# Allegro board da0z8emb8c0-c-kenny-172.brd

Outline 225.17 x 128 mm; copper layers: TOP, SGND, IN1, IN2, SVCC, IN3, SGND1, BOTTOM. Coordinates in mm from the lower left corner of the outline.

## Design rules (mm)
constraint set DEFAULT: min track width 0.102
net group DFP-S4.5W4(3.5)-T123B: nets INT_HDMI_AUXN INT_HDMI_AUXP
net group W10-T123B: nets FAN_PWM FAN_PWM_C
net group DFP-S3.5W4(3.5)-T13B: nets CLKA0 CLKA0B CLKA1 CLKA1B M_A_DQSN0 M_A_DQSN1 M_A_DQSN2 M_A_DQSN3 M_A_DQSN4 M_A_DQSN5 M_A_DQSN6 M_A_DQSN7 M_A_DQSP0 M_A_DQSP1 M_A_DQSP2 M_A_DQSP3 M_A_DQSP4 M_A_DQSP5 M_A_DQSP6 M_A_DQSP7 M_B_DQSN0 M_B_DQSN1 M_B_DQSN2 M_B_DQSN3 M_B_DQSN4 M_B_DQSN5 M_B_DQSN6 M_B_DQSN7 M_B_DQSP0 M_B_DQSP1 M_B_DQSP2 M_B_DQSP3 M_B_DQSP4 M_B_DQSP5 M_B_DQSP6 M_B_DQSP7 WCKA0_0 WCKA0_1 WCKA0B_0 WCKA0B_1 WCKA1_0 WCKA1_1 WCKA1B_0 WCKA1B_1
net group DFP-S4.5W4(3.5)-T13B: nets C_IN_CLK#_R C_IN_CLK_R C_TX0_HDMI+_R C_TX0_HDMI-_R C_TX1_HDMI+_R C_TX1_HDMI-_R C_TX2_HDMI+_R C_TX2_HDMI-_R CLK_PCIE_LANN_R CLK_PCIE_LANP_R CLK_PCIE_SSDN_C CLK_PCIE_SSDN_R CLK_PCIE_SSDP_C CLK_PCIE_SSDP_R CLK_PCIE_WLANN_R CLK_PCIE_WLANP_R GFX_TX0N_C GFX_TX0P_C GFX_TX1N_C GFX_TX1P_C GFX_TX2N_C GFX_TX2P_C GFX_TX3N_C GFX_TX3P_C IN_CLK IN_CLK# IN_D0 IN_D0# IN_D1 IN_D1# IN_D2 IN_D2# INT_EDP_AUXN INT_EDP_AUXN_C INT_EDP_AUXP INT_EDP_AUXP_C INT_EDP_TXN0 INT_EDP_TXN0_C INT_EDP_TXN1 INT_EDP_TXN1_C INT_EDP_TXN2 INT_EDP_TXN2_C INT_EDP_TXN3 INT_EDP_TXN3_C INT_EDP_TXP0 INT_EDP_TXP0_C INT_EDP_TXP1 INT_EDP_TXP1_C INT_EDP_TXP2 INT_EDP_TXP2_C INT_EDP_TXP3 INT_EDP_TXP3_C INT_HDMICLK+_OUT INT_HDMICLK-_OUT INT_HDMITX0N_OUT INT_HDMITX0P_OUT INT_HDMITX1N_OUT INT_HDMITX1P_OUT INT_HDMITX2N_OUT INT_HDMITX2P_OUT PCIE_RXN0_SSD PCIE_RXN3_SSD PCIE_RXN4_LAN PCIE_RXN5_WLAN PCIE_RXN13_SSD_C PCIE_RXN14_SSD_C PCIE_RXN15_SSD_C PCIE_RXN16_SSD_C PCIE_RXN_LAN_L PCIE_RXP0_SSD PCIE_RXP3_SSD PCIE_RXP4_LAN PCIE_RXP5_WLAN PCIE_RXP13_SSD_C PCIE_RXP14_SSD_C PCIE_RXP15_SSD_C PCIE_RXP16_SSD_C PCIE_RXP_LAN_L PCIE_TXN0_SSD PCIE_TXN0_SSD_C PCIE_TXN1_SSD PCIE_TXN1_SSD_C PCIE_TXN2_SSD PCIE_TXN2_SSD_C PCIE_TXN3_SSD PCIE_TXN3_SSD_C PCIE_TXN4_LAN PCIE_TXN4_LAN_C PCIE_TXN5_WLAN PCIE_TXN5_WLAN_C PCIE_TXP0_SSD PCIE_TXP0_SSD_C PCIE_TXP1_SSD PCIE_TXP1_SSD_C PCIE_TXP2_SSD PCIE_TXP2_SSD_C PCIE_TXP3_SSD PCIE_TXP3_SSD_C PCIE_TXP4_LAN PCIE_TXP4_LAN_C PCIE_TXP5_WLAN PCIE_TXP5_WLAN_C PEG_RXN0 PEG_RXN0_C PEG_RXN1 PEG_RXN1_C PEG_RXN2 PEG_RXN2_C PEG_RXN3 PEG_RXN3_C PEG_RXP0 PEG_RXP0_C PEG_RXP1 PEG_RXP1_C PEG_RXP2 PEG_RXP2_C PEG_RXP3 PEG_RXP3_C PEG_TXN0 PEG_TXN1 PEG_TXN2 PEG_TXN3 PEG_TXP0 PEG_TXP1 PEG_TXP2 PEG_TXP3 USB3_SS0RX+ USB3_SS0RX+_RE USB3_SS0RX+_RE_C USB3_SS0RX- USB3_SS0RX-_RE USB3_SS0RX-_RE_C USB3_SS0TX+ USB3_SS0TX+_RE USB3_SS0TX+_RE_C USB3_SS0TX- USB3_SS0TX-_RE USB3_SS0TX-_RE_C USB30_RX0+ USB30_RX0- USB30_RX1+ USB30_RX1+_C USB30_RX1- USB30_RX1-_C USB30_RX2+ USB30_RX2+_C USB30_RX2- USB30_RX2-_C USB30_RX3+ USB30_RX3- USB30_RX+_TYPEC1 USB30_RX+_TYPEC2 USB30_RX-_TYPEC1 USB30_RX-_TYPEC2 USB30_TX0+ USB30_TX0- USB30_TX1+ USB30_TX1+_C USB30_TX1+_C_R USB30_TX1- USB30_TX1-_C USB30_TX1-_C_R USB30_TX2+ USB30_TX2+_C USB30_TX2+_C_R USB30_TX2- USB30_TX2-_C USB30_TX2-_C_R USB30_TX3+ USB30_TX3- USB30_TX+_TYPEC1 USB30_TX+_TYPEC1_C USB30_TX+_TYPEC2 USB30_TX+_TYPEC2_C USB30_TX-_TYPEC1 USB30_TX-_TYPEC1_C USB30_TX-_TYPEC2 USB30_TX-_TYPEC2_C
net group DFP-S6(5)W6.5(5.5)-T13B: nets M_A_CLKN0 M_A_CLKN1 M_A_CLKP0 M_A_CLKP1 M_B_CLKN0 M_B_CLKP0
net group DFP-S6(5.5)W4(3.5)-T13B: nets SATA_RXN0 SATA_RXN0_CN SATA_RXN0_IN SATA_RXN1 SATA_RXN1A_C SATA_RXN_OUT SATA_RXP0 SATA_RXP0_CN SATA_RXP0_IN SATA_RXP1 SATA_RXP1A_C SATA_RXP_OUT SATA_TXN0 SATA_TXN0_CN SATA_TXN0_IN SATA_TXN1 SATA_TXN1A_C SATA_TXN_OUT SATA_TXP0 SATA_TXP0_CN SATA_TXP0_IN SATA_TXP1 SATA_TXP1A_C SATA_TXP_OUT USB1_DM0-_HUB USB1_DM0-_HUB_R USB1_DP0+_HUB USB1_DP0+_HUB_R USBP0+ USBP0- USBP1+_C USBP1+_C_R USBP1+_U14 USBP1-_C USBP1-_C_R USBP1-_U14 USBP2+ USBP2+_C USBP2- USBP2-_C USBP3+ USBP3- USBP4+_DB USBP4-_DB USBP5+_CAM USBP5+_CAM_C USBP5-_CAM USBP5-_CAM_C USBP7+_FP USBP7+_FP_HUB USBP7-_FP USBP7-_FP_HUB USBP8+_TS USBP8-_TS USBP8_TS+_C USBP8_TS-_C USBP_TYPC+_C USBP_TYPC-_C
net group DFP-S11.5(11: nets MDI0+ MDI0+_1 MDI0- MDI0-_1 MDI1+ MDI1+_1 MDI1- MDI1-_1 MDI2+ MDI2+_1 MDI2- MDI2-_1 MDI3+ MDI3+_1 MDI3- MDI3-_1
net group GND: nets GND
net group W4(3.5)-T13B: nets ACZ_RST#_AUDIO ACZ_SDIN0 ACZ_SDOUT_AUDIO ACZ_SYNC_AUDIO BIT_CLK_AUDIO DMIC_CLK DMIC_CLK_L DMIC_DAT DMIC_DAT_L EMMC_CLK EMMC_CLK_R EMMC_CMD EMMC_CMD_R EMMC_DAT0 EMMC_DAT0_R EMMC_DAT1 EMMC_DAT1_R EMMC_DAT2 EMMC_DAT2_R EMMC_DAT3 EMMC_DAT3_R EMMC_DAT4 EMMC_DAT4_R EMMC_DAT5 EMMC_DAT5_R EMMC_DAT6 EMMC_DAT6_R EMMC_DAT7 EMMC_DAT7_R EMMC_RCLK EMMC_RCLK_R M_A_DM0 M_A_DM1 M_A_DM2 M_A_DM3 M_A_DM4 M_A_DM5 M_A_DM6 M_A_DM7 M_A_DQ0 M_A_DQ1 M_A_DQ2 M_A_DQ3 M_A_DQ4 M_A_DQ5 M_A_DQ6 M_A_DQ7 M_A_DQ8 M_A_DQ9 M_A_DQ10 M_A_DQ11 M_A_DQ12 M_A_DQ13 M_A_DQ14 M_A_DQ15 M_A_DQ16 M_A_DQ17 M_A_DQ18 M_A_DQ19 M_A_DQ20 M_A_DQ21 M_A_DQ22 M_A_DQ23 M_A_DQ24 M_A_DQ25 M_A_DQ26 M_A_DQ27 M_A_DQ28 M_A_DQ29 M_A_DQ30 M_A_DQ31 M_A_DQ32 M_A_DQ33 M_A_DQ34 M_A_DQ35 M_A_DQ36 M_A_DQ37 M_A_DQ38 M_A_DQ39 M_A_DQ40 M_A_DQ41 M_A_DQ42 M_A_DQ43 M_A_DQ44 M_A_DQ45 M_A_DQ46 M_A_DQ47 M_A_DQ48 M_A_DQ49 M_A_DQ50 M_A_DQ51 M_A_DQ52 M_A_DQ53 M_A_DQ54 M_A_DQ55 M_A_DQ56 M_A_DQ57 M_A_DQ58 M_A_DQ59 M_A_DQ60 M_A_DQ61 M_A_DQ62 M_A_DQ63 M_A_EVENT# M_A_RST# M_B_DM0 M_B_DM1 M_B_DM2 M_B_DM3 M_B_DM4 M_B_DM5 M_B_DM6 M_B_DM7 M_B_DQ0 M_B_DQ1 M_B_DQ2 M_B_DQ3 M_B_DQ4 M_B_DQ5 M_B_DQ6 M_B_DQ7 M_B_DQ8 M_B_DQ9 M_B_DQ10 M_B_DQ11 M_B_DQ12 M_B_DQ13 M_B_DQ14 M_B_DQ15 M_B_DQ16 M_B_DQ17 M_B_DQ18 M_B_DQ19 M_B_DQ20 M_B_DQ21 M_B_DQ22 M_B_DQ23 M_B_DQ24 M_B_DQ25 M_B_DQ26 M_B_DQ27 M_B_DQ28 M_B_DQ29 M_B_DQ30 M_B_DQ31 M_B_DQ32 M_B_DQ33 M_B_DQ34 M_B_DQ35 M_B_DQ36 M_B_DQ37 M_B_DQ38 M_B_DQ39 M_B_DQ40 M_B_DQ41 M_B_DQ42 M_B_DQ43 M_B_DQ44 M_B_DQ45 M_B_DQ46 M_B_DQ47 M_B_DQ48 M_B_DQ49 M_B_DQ50 M_B_DQ51 M_B_DQ52 M_B_DQ53 M_B_DQ54 M_B_DQ55 M_B_DQ56 M_B_DQ57 M_B_DQ58 M_B_DQ59 M_B_DQ60 M_B_DQ61 M_B_DQ62 M_B_DQ63 PCH_AZ_CODEC_SDIN0_R
net group W4(3.5)-T123B: nets 5V_HSMBCK 5V_HSMBDT 32K_X1 32K_X2 48M_X1 48M_X2 APU_DISP_ON APU_DPST_PWM APU_LVDS_BLON BRIGHT DISP_ON GPU_CLR_REQ6# HDMI_HPD HDMI_HPD_C HDMI_HPD_Q HDMI_SCLK HDMI_SDATA LAN_XTAL1 PCH_BLON_C PCIE_CLKREQ_LAN# PCIE_CLKREQ_WLAN# SI_XTALIN SI_XTALOUT SL_CLK_100M SSD_PCIE_CLKREQ# ULT_EDP_HPD ULT_EDP_HPD_R XIN XOUT XTAL1 XTAL2 XTAL2_R XTALIN XTALOUT
net group W4-T13B: nets APU_SPI_CLK APU_SPI_CLK_R APU_SPI_CLK_TPM APU_SPI_CS0# APU_SPI_CS0#_R APU_SPI_HOLD# APU_SPI_SI APU_SPI_SI_R APU_SPI_SI_TPM APU_SPI_SO APU_SPI_SO_R APU_SPI_SO_TPM APU_SPI_WP APU_SPI_WP_R APU_SVC APU_SVD APU_SVT EC_SPI1_CLK EC_SPI1_CLK_ER EC_SPI1_CLK_R EC_SPI1_SI EC_SPI1_SI_ER EC_SPI1_SI_R EC_SPI1_SO EC_SPI1_SO_ER EC_SPI1_SO_R EC_SPI_CS0# EC_SPI_CS0#_ER EC_SPI_CS0#_R EC_SPI_HOLD# EC_SPI_WP# EC_SPI_WP#_R ESPI_0 ESPI_0_R ESPI_1 ESPI_1_R ESPI_2 ESPI_2_R ESPI_3 ESPI_3_R ESPI_CLK ESPI_CLK_R ESPI_CS# ESPI_CS#_R ESPI_RESET# LAD0 LAD1 LAD2 LAD3 LFRAME_L LPC_PD_L LPCCLK LPCCLK_RUN_L LPCCLK_RUN_L_R PLTRST#_EC PROCHOT_EC SERIRQ SERIRQ_R SPI_TPM_CS SPI_TPM_CS_TPM SVC_APU SVD_APU SVT_APU
net group W5(4.5)-T13B: nets ADBIA0 ADBIA1 CASA0B CASA1B CKEA0 CKEA1 CSA0B_0 CSA1B_0 DDBIA0_0 DDBIA0_1 DDBIA0_2 DDBIA0_3 DDBIA1_0 DDBIA1_1 DDBIA1_2 DDBIA1_3 DQA0_0 DQA0_1 DQA0_2 DQA0_3 DQA0_4 DQA0_5 DQA0_6 DQA0_7 DQA0_8 DQA0_9 DQA0_10 DQA0_11 DQA0_12 DQA0_13 DQA0_14 DQA0_15 DQA0_16 DQA0_17 DQA0_18 DQA0_19 DQA0_20 DQA0_21 DQA0_22 DQA0_23 DQA0_24 DQA0_25 DQA0_26 DQA0_27 DQA0_28 DQA0_29 DQA0_30 DQA0_31 DQA1_0 DQA1_1 DQA1_2 DQA1_3 DQA1_4 DQA1_5 DQA1_6 DQA1_7 DQA1_8 DQA1_9 DQA1_10 DQA1_11 DQA1_12 DQA1_13 DQA1_14 DQA1_15 DQA1_16 DQA1_17 DQA1_18 DQA1_19 DQA1_20 DQA1_21 DQA1_22 DQA1_23 DQA1_24 DQA1_25 DQA1_26 DQA1_27 DQA1_28 DQA1_29 DQA1_30 DQA1_31 DRAM_RST_A EDCA0_0 EDCA0_1 EDCA0_2 EDCA0_3 EDCA1_0 EDCA1_1 EDCA1_2 EDCA1_3 MAA0_0 MAA0_1 MAA0_2 MAA0_3 MAA0_4 MAA0_5 MAA0_6 MAA0_7 MAA0_8 MAA1_0 MAA1_1 MAA1_2 MAA1_3 MAA1_4 MAA1_5 MAA1_6 MAA1_7 MAA1_8 RASA0B RASA1B WEA0B WEA1B
net group W5-T13B: nets CPU_VDD0_RUN_FB_H CPU_VDD0_RUN_FB_L CPU_VDDNB_RUN_FB_H CPU_VDDP_RUN_FB_H CPU_VDDP_RUN_FB_L
net group W6.5(5.5)-T13B: nets M_A_A0 M_A_A1 M_A_A2 M_A_A3 M_A_A4 M_A_A5 M_A_A6 M_A_A7 M_A_A8 M_A_A9 M_A_A10 M_A_A11 M_A_A12 M_A_A13 M_A_ACT# M_A_ALERT# M_A_BG#0 M_A_BG#1 M_A_BS#0 M_A_BS#1 M_A_CAS# M_A_CKE0 M_A_CKE1 M_A_CS#0 M_A_CS#1 M_A_ODT0 M_A_ODT1 M_A_PARITY M_A_RAS# M_A_WE#
net group W6.5(5.25)-T13B: nets M_B_BG#1_R0 M_B_BG#1_R1 M_B_BG#1_R2 M_B_BG#1_R3
net group W6.5(5.25)-T123B: nets M_B_A0 M_B_A1 M_B_A2 M_B_A3 M_B_A4 M_B_A5 M_B_A6 M_B_A7 M_B_A8 M_B_A9 M_B_A10 M_B_A11 M_B_A12 M_B_A13 M_B_ACT# M_B_ALERT# M_B_BG#0 M_B_BG#1 M_B_BS#0 M_B_BS#1 M_B_CAS# M_B_CKE0 M_B_CS#0 M_B_ODT0 M_B_PARITY M_B_RAS# M_B_WE#
net group W8-T123B: nets +1.05V_LAN +5V_PVDD +5VA +AZA_VDD AVDD2 DVDD_IO
net group W12-T123B: nets +3V_EC +3V_LDO_EC +A3VPCU
net group W15-T123B: nets HP-L2 HP-L3 HP-R2 HP-R3 HP_JD# LINE1-L LINE1-R LINE1-VREFO-L LINE1-VREFO-R MIC2-VREFO MVREFDA MVREFDB SENSEA
net group W20-T123B: nets 5447_CC1_CON 5447_CC2_CON +1.5V_RTC +1.8V_SW +1.8V_TPM +1.8V_TPM_VSB +3V_DMIC +3V_GFX +3V_LAN +3V_USB +3V_USB_D +3VPCU +3VPCU_EC +3VPCU_ECPLL +3VPCU_HALL +3VRTC +5V_HDMIC +5V_KB +APU_VDD_33 +APU_VDD_33_S5 +APU_VDDIO_AZ +BAT_RTC +G_SEN_PW +VCCRTC_2 +VDDQ +VDDQ_VTT +VREF_CA0 +VREF_CA1 ECROM_PWR EMMC_VDDI_BYP PBA_PWR PBA_PWR_C PBA_PWR_R VDDBT_RTC VREFC_A0 VREFC_A1 VREFD1_A0 VREFD1_A1 VREFD2_A0 VREFD2_A1 VSTBY_FSPI
net group W30-T123B: nets +VDD_18_S5
net group W40-T123B: nets +0.95VS5 L_SPK+ L_SPK+_1 L_SPK- L_SPK-_1 R_SPK+ R_SPK+_1 R_SPK- R_SPK-_1 RING2 SLEEVE
net group W60-T123B: nets 1.8V_PU9 3.3V_PU9 +1.05V_LAN_REGOUT
net group W65-T123B: nets +601_VCC
net group W70-T123B: nets USBPWRD2
net group W80-T123B: nets +USBPWR0 +USBPWR1 +VIN_BLIGHT
net group W99-T123B: nets +3V_SSD +3V_WLAN_P +3VLCD_CON +3VLCD_CON_R +3VLCD_CON_R_C +5VODD +TYPEC_VBUS

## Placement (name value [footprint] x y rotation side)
C17  4.7u/25V_6  [C0603]  62.72 109.84 90 top
C22  0.1u/16V_4  [C0402]  47.94 109.46 270 top
C23  10u/6.3V_6  [C0603]  47.05 112.13 270 top
C24  *0.1u/16V_4  [C0402]  49.26 112 90 top
C25  0.1u/16V_4  [C0402]  48.27 112 90 top
C28  0.1u/16V_4  [C0402]  54.8 108.57 0 top
C29  *0.1u/16V_4  [C0402]  52.26 113.02 90 top
C30  *4.7u/6.3V_4  [C0402]  40.19 109.21 0 top
C31  *4.7u/6.3V_4  [C0402]  43.75 100.95 0 top
C32  15p/50V_4  [C0402]  43.62 110.98 0 top
C33  15p/50V_4  [C0402]  45.43 110.98 0 top
C37  1000p/50V_4  [C0402]  53.02 108.6 0 top
C39  0.1u/16V_4  [C0402]  43.75 109.59 270 top
C42  0.1u/16V_4  [C0402]  43.75 99.81 0 top
C43  0.1u/10V_2  [C0201]  54.06 103.49 270 bottom
C45  0.1u/16V_4  [C0402]  42.48 109.59 270 top
C51  0.1u/16V_4  [C0402]  40.19 108.06 0 top
C53  0.1u/10V_2  [C0201]  55.18 103.49 270 bottom
C58  0.1u/16V_4  [C0402]  49.34 107.17 90 top
C61  33p/50V_4  [C0402]  56.7 107.17 270 top
C62  0.1u/25V_4  [C0402]  60.54 108.49 0 top
C64  0.1u/16V_4  [C0402]  40.75 106.54 270 bottom
C65  0.1u/16V_4  [C0402]  50.35 107.17 90 top
C67  1000p/50V_4  [C0402]  60.54 107.53 0 top
C88  0.1u/16V_4  [C0402]  48.83 102.09 90 top
C91  180p/50V_4  [C0402]  57.49 103.57 270 bottom
C93  1u/6.3V_4  [C0402]  41.72 102.48 180 top
C94  0.1u/16V_4  [C0402]  47.81 102.09 90 top
C97  0.01u/50V_4  [C0402]  28.26 102.35 0 top
C106  0.1u/16V_4  [C0402]  60.89 103.39 180 top
C112  *0.1u/25V_6  [C0603]  65.09 100.32 0 top
C113  *22U/6.3V_6  [C0603]  61.28 102.2 180 top
C146  *MMC@1u/6.3V_2  [C0201]  71.82 28.69 0 bottom
C147  *MMC@4.7u/10V_4  [C0402]  69.78 31.86 180 bottom
C148  *MMC@4.7u/10V_4  [C0402]  69.4 35.67 180 bottom
C149  *MMC@0.1u/10V_2  [C0201]  65.72 33.26 270 bottom
C150  *MMC@0.1u/10V_2  [C0201]  66.74 31.48 180 bottom
C180  *HDMI_R@0.1u/16V_4  [C0402]  23.05 73.01 90 top
C181  *HDMI_R@0.1u/16V_4  [C0402]  21.91 73.01 90 top
C182  HDMI_R@0.1u/16V_4  [C0402]  23.94 86.6 270 top
C183  220p/50V_4  [C0402]  14.41 88.25 180 top
C205  0.1u/16V_4  [C0402]  21.27 76.06 180 top
C210  HDMI_R@0.1u/16V_4  [C0402]  19.37 81.52 0 top
C212  HDMI_R@0.1u/16V_4  [C0402]  21.27 74.92 0 top
C222  *HDMI_R@0.1u/16V_4  [C0402]  21.27 81.52 180 top
C239  *10p/50V_4  [C0402]  20.76 88 0 top
C249  *10p/50V_4  [C0402]  22.54 88 180 top
C270  *1.6p/50V_4  [C0402]  21.4 59.04 270 top
C272  0.22u/6.3V_2  [C0201]  24.32 58.66 0 top
C277  0.22u/6.3V_2  [C0201]  24.32 57.64 0 top
C280  *1.6p/50V_4  [C0402]  21.4 57.26 90 top
C287  *1.6p/50V_4  [C0402]  23.61 55.74 90 top
C295  *1.6p/50V_4  [C0402]  23.61 53.96 270 top
C304  0.1u/16V_4  [C0402]  17.05 51.6 180 top
C310  470p/50V_4  [C0402]  17.05 50.58 180 top
C323  100p/50V_4  [C0402]  209.1 38.59 180 bottom
C327  100p/50V_4  [C0402]  210.88 38.59 180 bottom
C328  1u/10V_4  [C0402]  17.21 46.09 0 top
C332  100p/50V_4  [C0402]  210.63 35.17 0 bottom
C333  4.7u/6.3V_6  [C0603]  207.96 34.53 270 bottom
C334  4.7u/6.3V_6  [C0603]  206.44 35.67 270 bottom
C340  100p/50V_4  [C0402]  210.63 33.26 0 bottom
C343  *1000p/50V_4  [C0402]  215.71 42.53 180 top
C345  *1.6p/50V_4  [C0402]  21.78 39.23 270 top
C349  0.22u/6.3V_2  [C0201]  24.57 38.85 0 top
C351  0.22u/6.3V_2  [C0201]  24.57 37.83 0 top
C352  *1.6p/50V_4  [C0402]  21.78 37.45 90 top
C363  *1.6p/50V_4  [C0402]  23.43 33.9 90 top
C364  0.1u/10V_2  [C0201]  169.61 31.74 90 top
C365  0.1u/10V_2  [C0201]  173.09 31.58 0 top
C366  *0.1u/16V_4  [C0402]  207.07 31.96 270 top
C367  180p/50V_4  [C0402]  180.91 29.83 0 top
C368  *1.6p/50V_4  [C0402]  23.43 32.12 270 top
C370  0.1u/16V_2  [C0201]  163 31.23 0 top
C371  180p/50V_4  [C0402]  165.16 31.86 270 top
C372  0.1u/10V_2  [C0201]  167.07 31.74 90 top
C373  22p/50V_4  [C0402]  160.08 29.58 0 top
C374  1u/6.3V_2  [C0201]  163 31.99 180 top
C375  *10u/6.3V_6  [C0603]  204.91 31.99 180 top
C377  *1u/10V_4  [C0402]  201.99 20.15 90 top
C378  *0.1u/16V_4  [C0402]  200.98 27.29 90 top
C379  *10u/6.3V_6  [C0603]  199.71 26.91 270 top
C381  180p/50V_4  [C0402]  163.51 34.91 270 top
C384  180p/50V_4  [C0402]  183.58 28.43 270 top
C385  10u/6.3V_4  [C0402]  197.8 27.55 0 top
C386  0.1u/10V_2  [C0201]  183.58 26.28 0 top
C387  180p/50V_4  [C0402]  183.96 24.24 0 top
C388  0.1u/10V_2  [C0201]  166.81 25.13 180 bottom
C389  *10p/50V_4  [C0402]  165.54 21.7 0 bottom
C390  180p/50V_4  [C0402]  183.58 22.72 270 top
C391  *TPM@10u/6.3V_6  [C0603]  130.74 23.1 270 top
C392  *TPM@0.1u/10V_2  [C0201]  129.6 22.85 90 top
C393  *PBA@0.01u/50V_4  [C0402]  53 16.47 270 bottom
C394  220p/25V_2  [C0201]  149.54 17.26 90 top
C395  *GS@0.1u/10V_2  [C0201]  62.42 23.35 0 top
C396  1000p/50V_4  [C0402]  116.27 21.45 270 top
C397  1000p/50V_4  [C0402]  117.28 21.45 270 top
C398  1000p/50V_4  [C0402]  118.3 21.45 270 top
C399  1000p/50V_4  [C0402]  119.31 21.45 270 top
C400  220p/25V_2  [C0201]  148.55 17.48 0 top
C401  220p/25V_2  [C0201]  171 19.16 90 bottom
C402  220p/25V_2  [C0201]  172.02 19.16 90 bottom
C403  220p/25V_2  [C0201]  172.91 19.16 90 bottom
C404  220p/25V_2  [C0201]  169.48 19.42 90 bottom
C405  220p/25V_2  [C0201]  170.24 19.16 90 bottom
C406  220p/25V_2  [C0201]  168.72 19.42 90 bottom
C407  220p/25V_2  [C0201]  150.3 17.26 90 top
C408  220p/25V_2  [C0201]  151.06 17.26 90 top
C409  220p/25V_2  [C0201]  151.95 17.26 90 top
C410  220p/25V_2  [C0201]  152.97 17.26 90 top
C411  220p/25V_2  [C0201]  153.99 17.26 90 top
C412  220p/25V_2  [C0201]  166.05 19.16 90 bottom
C413  *TPM@0.1u/10V_2  [C0201]  121.6 17.64 0 top
C414  220p/25V_2  [C0201]  155 17.26 90 top
C415  220p/25V_2  [C0201]  156.02 17.26 90 top
C416  220p/25V_2  [C0201]  157.03 17.26 90 top
C417  220p/25V_2  [C0201]  157.8 17.26 90 top
C418  220p/25V_2  [C0201]  159.95 17.26 90 top
C419  220p/25V_2  [C0201]  158.56 17.26 90 top
C420  220p/25V_2  [C0201]  161 17.26 90 top
C421  220p/25V_2  [C0201]  161.75 17.26 90 top
C422  220p/25V_2  [C0201]  162.49 17.26 90 top
C423  220p/25V_2  [C0201]  163.26 17.26 90 top
C424  220p/25V_2  [C0201]  167.96 19.42 90 bottom
C425  *PBA@2.2u/16V_6  [C0603]  49.59 22.31 180 bottom
C426  *TPC@0.1u/25V_4  [C0402]  11.24 19.42 0 bottom
C427  220p/25V_2  [C0201]  165.03 19.16 90 bottom
C428  0.01u/10V_2  [C0201]  209.23 20.43 90 top
C429  0.01u/10V_2  [C0201]  209.99 20.43 90 top
C430  0.01u/10V_2  [C0201]  210.75 20.43 90 top
C431  0.01u/10V_2  [C0201]  211.52 20.43 90 top
C432  *TPM@0.1u/10V_2  [C0201]  121.6 18.4 0 top
C433  0.1u/16V_4  [C0402]  183.58 19.93 270 top
C434  1000p/50V_4  [C0402]  185.23 18.66 270 top
C435  1u/6.3V_4  [C0402]  169.48 21.83 90 bottom
C436  *GS@10u/6.3V_4  [C0402]  62.04 20.05 270 top
C437  *180p/50V_4  [C0402]  165.54 20.56 180 bottom
C438  *TPC@390p/50V_4  [C0402]  11.24 18.4 0 top
C439  *10p/50V_4  [C0402]  72.83 19.49 180 top
C440  0.1u/16V_4  [C0402]  163.26 20.69 270 top
C441  *TPC@0.1u/16V_4  [C0402]  23.68 17.39 90 bottom
C442  0.1u/10V_2  [C0201]  162.75 18.27 270 top
C443  0.1u/10V_2  [C0201]  163.51 18.27 270 top
C445  *TPM@0.1u/10V_2  [C0201]  129.6 18.27 90 top
C446  *TPM@10u/6.3V_6  [C0603]  130.74 18.02 270 top
C447  *GS@0.1u/10V_2  [C0201]  62.42 18.4 270 top
C449  0.1u/10V_2  [C0201]  213.93 17.64 0 top
C450  0.1u/10V_2  [C0201]  212.81 18.53 90 top
C451  0.1u/10V_2  [C0201]  213.55 18.53 90 top
C453  100p/50V_4  [C0402]  183.45 17.51 0 top
C454  0.1u/16V_4  [C0402]  216.6 16.5 180 top
C455  *PBA@0.01u/50V_4  [C0402]  53.83 22.16 90 bottom
C456  *PBA@4.7u/6.3V_4  [C0402]  54.8 22.16 90 bottom
C457  10u/6.3V_6  [C0603]  184.34 16.24 0 top
C458  *TPC@22u/6.3V_6  [C0603]  15.68 23.61 0 top
C459  *TPC@22u/6.3V_6  [C0603]  15.68 25.13 0 top
C460  *10p/50V_4  [C0402]  70.93 19.49 0 top
C461  10u/6.3V_4  [C0402]  214.06 16.37 270 top
C462  *TPC@0.1u/25V_4  [C0402]  11.62 12.81 0 bottom
C464  *GS@33p/50V_4  [C0402]  67.75 16.62 180 top
C465  *10u/6.3V_4  [C0402]  216.09 14.08 90 top
C466  0.1u/10V_2  [C0201]  208.04 13.7 0 top
C467  *GS@33p/50V_4  [C0402]  66.1 15.1 180 top
C468  0.01u/10V_2  [C0201]  209.1 12.56 90 top
C469  0.01u/10V_2  [C0201]  209.87 12.56 90 top
C470  0.01u/10V_2  [C0201]  210.63 12.56 90 top
C471  0.01u/10V_2  [C0201]  211.39 12.56 90 top
C476  0.1u/10V_2  [C0201]  208.04 12.81 0 top
C477  0.1u/10V_2  [C0201]  173.92 12.38 180 top
C478  0.1u/10V_2  [C0201]  173.92 11.67 180 top
C479  10u/6.3V_4  [C0402]  207.45 11.67 180 top
C480  180p/50V_4  [C0402]  183.58 13.7 270 top
C489  *SSD@0.1u/16V_2  [C0201]  24.19 4.56 180 top
C490  SSD@0.1u/16V_2  [C0201]  36.26 4.43 270 top
C491  *SSD@0.1u/16V_2  [C0201]  38.92 4.43 270 top
C498  *0.1u/6.3V_2  [C0201]  37.15 121.4 270 top
C508  0.1u/16V_4  [C0402]  38.8 121.91 90 bottom
C525  10p/3KV_1808  [C1808]  21.4 112.51 234 bottom
C526  0.1u/25V_4  [C0402]  64.7 106.41 90 top
C527  0.01u/50V_4  [C0402]  65.72 106.41 90 top
C528  10P/50V_4  [C0402]  41.82 105.27 270 bottom
C529  10P/50V_4  [C0402]  42.99 105.27 270 bottom
C530  0.1u/10V_2  [C0201]  47.56 103.26 270 bottom
C531  0.1u/10V_2  [C0201]  48.58 103.26 270 bottom
C532  180p/50V_4  [C0402]  60.01 110.22 90 top
C533  0.1u/10V_2  [C0201]  49.34 105.27 270 bottom
C534  0.1u/10V_2  [C0201]  50.35 105.27 270 bottom
C535  0.1u/10V_2  [C0201]  50.86 103.21 270 bottom
C536  0.1u/10V_2  [C0201]  51.88 103.21 270 bottom
C537  0.1u/10V_2  [C0201]  52.03 104.89 270 bottom
C538  0.1u/10V_2  [C0201]  53.05 104.89 270 bottom
C539  0.1u/16V_4  [C0402]  60.39 104.38 270 bottom
C540  100p/50V_4  [C0402]  61.4 104.38 90 bottom
C541  180p/50V_4  [C0402]  56.2 103.57 270 bottom
C542  0.1u/16V_4  [C0402]  60.59 102.53 0 bottom
C545  1u/6.3V_4  [C0402]  64.32 90.41 90 bottom
C549  0.01u/50V_4  [C0402]  65.59 94.6 180 bottom
C550  10u/6.3V_4  [C0402]  63.31 93.97 0 bottom
C551  0.1u/16V_4  [C0402]  63.31 92.82 0 bottom
C558  HDMI_R@0.1u/16V_4  [C0402]  19.75 83.17 0 bottom
C559  *220p/50V_4  [C0402]  15.68 83.55 180 top
C560  0.1u/16V_4  [C0402]  21.65 83.17 180 bottom
C593  0.1u/16V_4  [C0402]  20.46 55.23 90 bottom
C599  100u/6.3V_12  [C1206]  21.03 53.22 0 bottom
C604  0.1u/16V_4  [C0402]  15.17 45.45 180 bottom
C608  470p/50V_4  [C0402]  15.17 44.44 180 bottom
C609  0.1u/16V_4  [C0402]  15.17 43.42 180 bottom
C610  1u/6.3V_4  [C0402]  22.79 42.66 90 bottom
C612  100u/6.3V_12  [C1206]  18.98 41.39 0 bottom
C615  1u/10V_6  [C0603]  208.72 22.59 90 bottom
C616  2.2u/6.3V_4  [C0402]  208.72 27.67 0 bottom
C619  10u/6.3V_4  [C0402]  204.4 21.45 180 bottom
C620  10u/6.3V_4  [C0402]  208.72 29.83 180 bottom
C622  1u/10V_6  [C0603]  208.47 24.62 180 bottom
C623  0.1u/16V_4  [C0402]  208.09 31.86 270 bottom
C624  10u/6.3V_6  [C0603]  207.2 22.59 90 bottom
C627  10u/6.3V_4  [C0402]  206.94 31.86 270 bottom
C629  10u/6.3V_4  [C0402]  205.88 21.45 90 bottom
C635  10u/6.3V_4  [C0402]  203.39 32.24 270 bottom
C637  0.1u/16V_4  [C0402]  199.32 21.02 90 bottom
C638  256@0.1u/16V_4  [C0402]  202.12 32.29 270 bottom
C641  10u/6.3V_4  [C0402]  201.86 20.15 90 bottom
C643  *0.1u/16V_4  [C0402]  203.13 34.66 270 bottom
C644  *0.1u/16V_2  [C0201]  192.85 12.28 90 bottom
C645  0.1u/16V_2  [C0201]  193.79 12.28 90 bottom
C646  10u/6.3V_4  [C0402]  194.12 11.04 180 bottom
C647  0.1u/16V_4  [C0402]  203.01 20.15 90 bottom
C648  100p/50V_4  [C0402]  202.12 34.66 90 bottom
C650  10u/6.3V_4  [C0402]  199.68 19.54 0 bottom
C656  0.1u/16V_4  [C0402]  199.32 23.07 90 bottom
C659  10u/6.3V_4  [C0402]  197.55 26.28 0 bottom
C660  255@0.1u/16V_4  [C0402]  198.94 31.1 270 bottom
C661  0.1u/16V_4  [C0402]  197.67 27.93 0 bottom
C663  33p/50V_4  [C0402]  196.15 24.75 90 bottom
C666  10u/6.3V_4  [C0402]  198.23 23.07 90 bottom
C667  *22p/50V_4  [C0402]  197.55 25.13 180 bottom
C670  22U/6.3V_6  [C0603]  211.52 24.75 180 bottom
C671  *100u/6.3V_12  [C1206]  210.93 29.83 90 bottom
C672  470p/50V_4  [C0402]  215.83 29.2 0 top
C673  0.1u/16V_4  [C0402]  215.71 30.21 0 top
C674  0.1u/16V_4  [C0402]  215.83 28.05 0 top
C675  *TPC@0.1u/16V_4  [C0402]  28.38 21.2 270 top
C676  0.1u/10V_2  [C0201]  175.45 32.37 180 top
C679  0.1u/10V_2  [C0201]  165.92 25.01 90 bottom
C680  10P/50V_4  [C0402]  73.34 23.28 270 bottom
C681  10P/50V_4  [C0402]  74.48 23.23 270 bottom
C682  0.1u/16V_4  [C0402]  76.52 23.23 270 bottom
C683  *ODD@100u/6.3V_12  [C1206]  126.58 20.43 270 bottom
C684  *TPC@0.1u/16V_4  [C0402]  27.24 21.2 270 top
C685  *ODD@10u/6.3V_6  [C0603]  128.47 19.8 270 bottom
C686  *ODD@0.1u/16V_4  [C0402]  129.73 19.8 90 bottom
C687  *ODD@0.1u/16V_4  [C0402]  130.69 19.8 90 bottom
C688  *ODD@0.01u/50V_4  [C0402]  131.66 19.8 90 bottom
C689  *ODD@0.01u/50V_4  [C0402]  132.62 19.8 90 bottom
C690  *TPC@0.1u/16V_4  [C0402]  12.86 20.05 90 bottom
C691  *TPC@0.1u/16V_4  [C0402]  11.36 21.83 0 bottom
C692  *TPC@0.1u/16V_4  [C0402]  11.36 20.81 0 bottom
C693  *ODD@0.01u/50V_4  [C0402]  135.88 19.93 270 bottom
C694  *ODD@0.01u/50V_4  [C0402]  136.84 19.93 270 bottom
C695  TPC@0.1u/16V_4  [C0402]  30.67 21.2 270 top
C696  *ODD@0.01u/50V_4  [C0402]  133.64 19.93 270 bottom
C697  *ODD@0.01u/50V_4  [C0402]  134.61 19.93 270 bottom
C698  1u/6.3V_4  [C0402]  211.14 18.27 90 bottom
C699  *ODD@15p/50V_4  [C0402]  124.27 14.97 90 bottom
C700  *TPC@0.1u/16V_4  [C0402]  29.53 21.2 270 top
C701  *10p/50V_4  [C0402]  193.25 13.4 180 bottom
C703  *ODD@180p/50V_4  [C0402]  123.25 14.97 90 bottom
C704  *TPC@47u/6.3V_8  [C0805]  18.1 22.72 90 top
C705  *KBL@2.2u/6.3V_6  [C0603]  199.07 18.15 180 bottom
C707  0.1u/16V_2  [C0201]  195.13 12.18 0 bottom
C708  *TPC@47u/6.3V_8  [C0805]  20.13 22.97 90 bottom
C710  *TPC@22u/6.3V_6  [C0603]  19.87 22.54 90 top
C711  *TPC@390p/50V_4  [C0402]  11.62 13.83 0 top
C713  *KBL@0.01u/50V_4  [C0402]  198.56 11.42 270 bottom
C714  *KBL@4.7u/6.3V_6  [C0603]  197.29 11.42 270 bottom
C715  0.1u/16V_2  [C0201]  191.96 11.16 270 bottom
C716  0.1u/16V_2  [C0201]  193.97 30.47 0 bottom
C717  *0.1u/16V_2  [C0201]  192.72 11.16 270 bottom
C718  *0.1u/16V_2  [C0201]  193.97 29.73 0 bottom
C719  10u/6.3V_4  [C0402]  192.97 31.36 90 bottom
C869  *HDT@0.01u/10V_2  [C0201]  120.84 49.39 180 bottom
C926  *HDT@0.01u/10V_2  [C0201]  111.31 47.61 90 bottom
C1104  0.1u/16V_4  [C0402]  17.08 74.54 0 bottom
C2185  EV@120P/50V_4  [C0402]  124.27 120.38 0 top
C2195  EV@1u/6.3V_2  [C0201]  148.98 89.9 0 top
C2196  EV@0.1u/10V_2  [C0201]  134.81 118.1 270 top
C2197  EV@1u/6.3V_2  [C0201]  148.98 109.97 0 top
C2198  EV@0.1u/10V_2  [C0201]  148.98 106.92 0 top
C2199  EV@0.1u/10V_2  [C0201]  142.43 99.4 90 top
C2207  EV@1u/6.3V_2  [C0201]  148.98 92.19 0 top
C2208  EV@0.1u/10V_2  [C0201]  148.98 88.76 0 top
C2209  EV@1u/6.3V_2  [C0201]  148.98 87.62 0 top
C2210  EV@1u/6.3V_2  [C0201]  144.59 95.36 180 top
C2211  EV@1u/6.3V_2  [C0201]  148.98 86.47 0 top
C2212  EV@0.1u/10V_2  [C0201]  148.98 84.19 0 top
C2213  EV@1u/6.3V_2  [C0201]  142.17 102.86 180 top
C2214  EV@1u/6.3V_2  [C0201]  146.62 106.39 0 top
C2215  EV@0.1u/10V_2  [C0201]  142.43 100.83 270 top
C2216  EV@1U/6.3V_4  [C0402]  139.86 116.01 180 top
C2217  EV@0.1u/10V_2  [C0201]  142.94 116.45 0 top
C2218  EV@1u/6.3V_2  [C0201]  145.67 116.74 270 top
C2219  EV@1u/6.3V_2  [C0201]  147.22 117.48 0 top
C2221  EV@1u/6.3V_2  [C0201]  148.02 114.37 270 top
C2223  EV@1u/6.3V_2  [C0201]  148.98 82.92 0 top
C2224  EV@1u/6.3V_2  [C0201]  148.98 85.33 0 top
C2225  EV@1u/6.3V_2  [C0201]  148.98 91.05 0 top
C2227  EV@1u/6.3V_2  [C0201]  132.78 118.1 270 top
C2228  EV@1u/6.3V_2  [C0201]  142.17 106.67 180 top
C2229  EV@1u/6.3V_2  [C0201]  148.98 108.95 0 top
C2231  EV@0.1u/10V_2  [C0201]  133.05 104.27 180 top
C2232  EV@1u/6.3V_2  [C0201]  144.74 113.42 90 top
C2233  EV@0.1u/10V_2  [C0201]  145.57 111.38 0 top
C2234  EV@0.1u/10V_2  [C0201]  144.77 109.57 270 top
C2235  EV@1u/6.3V_2  [C0201]  118.25 110.7 0 top
C2236  EV@1u/6.3V_2  [C0201]  104.84 110.48 90 top
C2237  EV@1u/6.3V_2  [C0201]  106.36 110.48 90 top
C2238  EV@1u/6.3V_2  [C0201]  107.5 110.98 90 top
C2239  EV@22u/6.3V_6  [C0603]  110.04 99.68 90 top
C2240  EV@0.1u/10V_2  [C0201]  146.97 109.35 0 top
C2241  EV@1u/6.3V_2  [C0201]  148.96 110.98 0 top
C2242  EV@1u/6.3V_2  [C0201]  142.35 81.9 0 top
C2243  EV@0.1u/10V_2  [C0201]  145.86 81.9 180 top
C2244  EV@1u/6.3V_2  [C0201]  146.62 111.38 180 top
C2245  EV@1u/6.3V_2  [C0201]  143.19 105.52 0 top
C2246  EV@22u/6.3V_6  [C0603]  118.58 108.57 180 top
C2247  EV@1u/6.3V_2  [C0201]  107.68 108.11 270 top
C2248  EV@1u/6.3V_2  [C0201]  108.7 108.11 270 top
C2249  EV@1u/6.3V_2  [C0201]  109.71 108.11 270 top
C2250  EV@22u/6.3V_6  [C0603]  104.74 107.86 90 top
C2251  EV@22u/6.3V_6  [C0603]  106.31 107.86 270 top
C2252  EV@0.1u/10V_2  [C0201]  143.92 106.3 0 top
C2253  EV@1u/6.3V_2  [C0201]  119.19 107.05 0 top
C2254  EV@1u/6.3V_2  [C0201]  117.26 106.92 0 top
C2255  EV@1u/6.3V_2  [C0201]  145.22 105.2 0 top
C2256  EV@1u/6.3V_2  [C0201]  114.95 105.32 90 top
C2257  EV@1u/6.3V_2  [C0201]  116.22 105.32 90 top
C2258  EV@1u/6.3V_2  [C0201]  117.36 105.32 270 top
C2259  EV@1u/6.3V_2  [C0201]  134.17 104.27 180 top
C2260  EV@1u/6.3V_2  [C0201]  135.28 104.27 0 top
C2261  EV@22u/6.3V_6  [C0603]  111.59 104.86 90 top
C2262  EV@22u/6.3V_6  [C0603]  113.35 104.86 90 top
C2263  EV@1u/6.3V_2  [C0201]  119.19 104.76 0 top
C2264  EV@22u/6.3V_6  [C0603]  104.84 104 270 top
C2265  EV@22u/6.3V_6  [C0603]  106.36 104 270 top
C2266  EV@0.1u/10V_2  [C0201]  133.64 118.1 270 top
C2267  EV@10u/6.3V_4  [C0402]  147.04 96.76 180 top
C2268  EV@10u/6.3V_4  [C0402]  147.25 104.38 0 top
C2269  EV@0.1u/10V_2  [C0201]  148.98 107.94 0 top
C2270  EV@1u/6.3V_2  [C0201]  141.54 104.63 180 top
C2271  *EV@330U_2.5V_3528  [C3528]  109 104.18 90 top
C2272  EV@1u/6.3V_2  [C0201]  116.09 103.92 180 top
C2273  EV@22u/6.3V_6  [C0603]  118.5 103.36 0 top
C2274  EV@1u/6.3V_2  [C0201]  113.93 102.48 90 top
C2275  EV@1u/6.3V_2  [C0201]  115.12 102.48 90 top
C2276  EV@1u/6.3V_2  [C0201]  104.84 101.97 90 top
C2277  EV@10u/6.3V_4  [C0402]  106.31 101.76 90 top
C2278  EV@22u/6.3V_6  [C0603]  113.73 100.34 270 top
C2279  EV@22u/6.3V_6  [C0603]  115.38 100.34 90 top
C2280  EV@1u/6.3V_2  [C0201]  117.41 98.28 180 top
C2281  EV@1u/6.3V_2  [C0201]  116.93 101.61 180 top
C2282  EV@22u/6.3V_6  [C0603]  108.62 99.68 90 top
C2283  EV@1u/6.3V_2  [C0201]  105.6 99.55 270 top
C2285  EV@1u/6.3V_2  [C0201]  106.36 99.55 270 top
C2286  EV@1u/6.3V_2  [C0201]  108.27 110.98 90 top
C2287  EV@1u/6.3V_2  [C0201]  109.03 110.98 90 top
C2288  EV@1u/6.3V_2  [C0201]  110.93 110.98 90 top
C2289  EV@1u/6.3V_2  [C0201]  109.79 110.98 90 top
C2290  EV@1u/6.3V_2  [C0201]  105.6 110.48 90 top
C2291  EV@1u/6.3V_2  [C0201]  118.43 96.89 0 top
C2295  0.1u/6.3V_2  [C0201]  58.35 26.78 180 top
C2296  180p/25V_2  [C0201]  58.35 27.67 0 top
C2297  0.1u/6.3V_2  [C0201]  58.35 28.56 180 top
C2298  EV@1u/6.3V_2  [C0201]  113.09 97.52 90 top
C2304  EV@1u/6.3V_2  [C0201]  108.67 97.4 90 top
C2305  EV@1u/6.3V_2  [C0201]  110.04 97.4 90 top
C2306  EV@1u/6.3V_2  [C0201]  110.93 97.4 90 top
C2307  EV@0.1u/10V_2  [C0201]  143 95.36 0 top
C2308  EV@1u/6.3V_2  [C0201]  145.74 95.36 180 top
C2310  1u/6.3V_4  [C0402]  50.73 31.36 180 top
C2311  10u/6.3V_4  [C0402]  50.73 30.34 0 top
C2312  EV@1u/6.3V_2  [C0201]  115.89 97.14 180 top
C2313  EV@0.1u/10V_2  [C0201]  147.45 94.59 0 top
C2315  *10u/6.3V_4  [C0402]  55.81 26.4 270 top
C2316  1u/6.3V_4  [C0402]  56.83 26.4 90 top
C2317  EV@0.1u/10V_2  [C0201]  143.44 94.22 0 top
C2318  0.1u/6.3V_2  [C0201]  47.69 31.74 0 top
C2319  0.1u/6.3V_2  [C0201]  47.69 30.97 0 top
C2320  EV@1u/6.3V_2  [C0201]  145.51 93.87 90 top
C2321  EV@1u/6.3V_2  [C0201]  133.57 93.36 270 top
C2322  0.1u/6.3V_2  [C0201]  56.59 31.44 270 top
C2323  0.1u/6.3V_2  [C0201]  57.47 31.44 270 top
C2340  EV@1u/6.3V_2  [C0201]  143.1 89.03 90 top
C2341  EV@1u/6.3V_2  [C0201]  144.78 89.26 0 top
C2342  EV@1u/6.3V_2  [C0201]  146.69 89.26 0 top
C2343  EV@1u/6.3V_2  [C0201]  145.04 87.08 0 top
C2344  EV@1u/6.3V_2  [C0201]  144.96 85.32 180 top
C2345  EV@1u/6.3V_2  [C0201]  143.44 81.9 180 top
C2346  EV@0.1u/10V_2  [C0201]  144.54 81.9 0 top
C2347  EV@0.1u/10V_2  [C0201]  146.98 81.89 0 top
C2349  0.01u/16V_2  [C0201]  50.73 78.73 180 top
C2350  0.01u/16V_2  [C0201]  42.35 78.85 90 top
C2351  1u/6.3V_4  [C0402]  30.29 78.35 270 top
C2352  0.22u/10V_2  [C0201]  34.35 55.49 180 top
C2368  0.1u/6.3V_2  [C0201]  50.23 54.09 0 top
C2369  1000p/25V_2  [C0201]  50.23 54.85 180 top
C2375  180p/25V_2  [C0201]  60.64 68.95 90 top
C2376  10u/6.3V_4  [C0402]  50.48 68.31 180 top
C2377  1u/6.3V_4  [C0402]  54.04 59.68 90 top
C2378  1u/6.3V_4  [C0402]  66.48 66.15 270 top
C2379  10u/6.3V_4  [C0402]  50.48 67.04 180 top
C2380  0.22u/10V_2  [C0201]  38.42 30.85 180 top
C2381  0.22u/10V_2  [C0201]  29.91 69.85 180 top
C2384  10u/6.3V_4  [C0402]  38.29 65.66 180 top
C2385  0.01u/16V_2  [C0201]  36 65.66 0 top
C2386  10u/6.3V_4  [C0402]  45.78 65.66 0 top
C2387  10u/6.3V_4  [C0402]  50.48 59.8 180 top
C2388  1u/6.3V_4  [C0402]  50.49 65.4 0 top
C2389  10u/6.3V_4  [C0402]  53.02 52.18 270 top
C2390  1u/6.3V_4  [C0402]  50.48 63.74 0 top
C2391  10u/6.3V_4  [C0402]  52.39 70.47 90 top
C2392  1u/6.3V_4  [C0402]  50.48 60.82 0 top
C2393  10u/6.3V_4  [C0402]  53.66 69.33 90 top
C2394  10u/6.3V_4  [C0402]  56.96 59.68 270 top
C2395  1u/6.3V_4  [C0402]  72.2 49.26 90 top
C2396  10u/6.3V_4  [C0402]  51.88 57.52 90 top
C2403  1u/6.3V_4  [C0402]  30.02 68.27 180 top
C2405  1u/6.3V_4  [C0402]  60.64 51.04 0 top
C2406  1u/6.3V_4  [C0402]  54.42 52.69 90 top
C2410  10u/6.3V_4  [C0402]  30.41 46.85 270 top
C2412  0.22u/10V_2  [C0201]  30.41 45.58 180 top
C2416  1u/6.3V_4  [C0402]  32.81 30.48 270 top
C2418  0.01u/16V_2  [C0201]  44.38 43.04 0 top
C2431  0.22u/10V_2  [C0201]  45.4 43.04 0 top
C2434  10u/6.3V_4  [C0402]  44.64 30.85 180 top
C2448  1u/6.3V_4  [C0402]  30.02 44.65 180 top
C2464  22u/6.3V_6  [C0603]  112.36 42.02 90 top
C2465  1u/6.3V_4  [C0402]  109.03 43.93 0 top
C2466  1u/6.3V_4  [C0402]  98.31 34.91 90 top
C2467  22u/6.3V_6  [C0603]  99.68 34.91 90 top
C2469  0.1u/6.3V_2  [C0201]  37.53 55.49 0 top
C2470  1000p/25V_2  [C0201]  38.03 42.91 180 top
C2471  180p/25V_2  [C0201]  91.53 66.31 90 top
C2472  1u/6.3V_4  [C0402]  88.53 66.43 270 top
C2473  22u/6.3V_6  [C0603]  88.96 59.42 180 top
C2474  22u/6.3V_6  [C0603]  88.91 64.2 270 top
C2475  22u/6.3V_6  [C0603]  89.72 61.56 270 top
C2476  22u/6.3V_6  [C0603]  86.68 59.73 90 top
C2477  22u/6.3V_6  [C0603]  86.68 65.01 270 top
C2478  22u/6.3V_6  [C0603]  90.1 66.92 270 top
C2479  22u/6.3V_6  [C0603]  86.68 62.37 90 top
C2480  180p/25V_2  [C0201]  96.71 50.41 90 top
C2481  1u/6.3V_4  [C0402]  95.79 50.46 270 top
C2482  1u/6.3V_4  [C0402]  94.83 50.46 270 top
C2483  1u/6.3V_4  [C0402]  110.93 42.4 90 top
C2484  22u/6.3V_6  [C0603]  102.68 39.36 180 top
C2485  1u/6.3V_4  [C0402]  91.88 48.22 0 top
C2486  1u/6.3V_4  [C0402]  91.88 47.26 0 top
C2487  1u/6.3V_4  [C0402]  91.93 50.46 270 top
C2488  22u/6.3V_6  [C0603]  113.78 42.02 90 top
C2489  22u/6.3V_6  [C0603]  93.53 65.26 180 top
C2490  180p/25V_2  [C0201]  91.12 58.89 0 top
C2491  0.22u/6.3V_2  [C0201]  88 56.53 180 top
C2492  0.22u/6.3V_2  [C0201]  86.68 55.36 270 top
C2493  0.22u/6.3V_2  [C0201]  88 57.29 180 top
C2494  0.22u/6.3V_2  [C0201]  86.68 57.77 90 top
C2495  180p/25V_2  [C0201]  88 58.36 0 top
C2496  180p/25V_2  [C0201]  86.68 56.76 90 top
C2497  1u/6.3V_4  [C0402]  109.41 42.4 90 top
C2498  1u/6.3V_4  [C0402]  95.26 32.14 270 top
C2499  10u/6.3V_4  [C0402]  99.88 27.04 270 top
C2500  1u/6.3V_4  [C0402]  69.4 66.15 270 top
C2501  1u/6.3V_4  [C0402]  55.18 69.33 270 top
C2502  180p/25V_2  [C0201]  86.68 54.22 270 top
C2503  22u/6.3V_6  [C0603]  95.82 58.41 90 top
C2504  22u/6.3V_6  [C0603]  93.41 58.66 180 top
C2505  22u/6.3V_6  [C0603]  94.32 63.74 180 top
C2506  22u/6.3V_6  [C0603]  95.72 55.1 90 top
C2507  22u/6.3V_6  [C0603]  95.82 61.07 90 top
C2508  22u/6.3V_6  [C0603]  93.41 61.07 180 top
C2509  1u/6.3V_4  [C0402]  87.06 50.41 0 top
C2510  1u/6.3V_4  [C0402]  87.06 49.44 0 top
C2511  22u/6.3V_6  [C0603]  83.91 26.91 180 top
C2512  0.22u/6.3V_2  [C0201]  100.01 30.47 90 top
C2513  1u/6.3V_4  [C0402]  99.88 29.07 90 top
C2514  1u/6.3V_4  [C0402]  88.71 50.02 270 top
C2515  1u/6.3V_4  [C0402]  88.33 48.37 0 top
C2516  22u/6.3V_6  [C0603]  94.42 33.9 180 top
C2517  0.1u/6.3V_2  [C0201]  96.33 29.2 180 top
C2522  22u/6.3V_6  [C0603]  98.11 60.95 90 top
C2523  22u/6.3V_6  [C0603]  69.66 49.52 90 top
C2524  22u/6.3V_6  [C0603]  64.98 66.15 270 top
C2525  22u/6.3V_6  [C0603]  63.41 66.15 270 top
C2526  22u/6.3V_6  [C0603]  88.07 52.21 90 top
C2527  22u/6.3V_6  [C0603]  64.83 49.52 90 top
C2528  22u/6.3V_6  [C0603]  66.61 49.52 90 top
C2529  22u/6.3V_6  [C0603]  68.13 49.52 90 top
C2530  22u/6.3V_6  [C0603]  88.07 54.85 270 top
C2531  1u/6.3V_4  [C0402]  89.72 50.02 270 top
C2532  1u/6.3V_4  [C0402]  89.22 46.85 0 top
C2533  22u/6.3V_6  [C0603]  89.75 30.85 180 top
C2534  1u/6.3V_4  [C0402]  92.9 50.46 270 top
C2535  1u/6.3V_4  [C0402]  93.86 50.46 270 top
C2536  1u/6.3V_4  [C0402]  110.68 45.33 270 top
C2537  1u/6.3V_4  [C0402]  90.16 48.25 180 top
C2538  1u/6.3V_4  [C0402]  90.74 50.02 270 top
C2539  22u/6.3V_6  [C0603]  91.78 30.97 90 top
C2545  22u/6.3V_6  [C0603]  67.91 66.15 270 top
C2546  22u/6.3V_6  [C0603]  97.6 58.13 90 top
C2547  22u/6.3V_6  [C0603]  90.49 55.79 90 top
C2548  22u/6.3V_6  [C0603]  93.46 52.21 180 top
C2549  22u/6.3V_6  [C0603]  93.46 55.36 180 top
C2550  22u/6.3V_6  [C0603]  93.46 57.01 180 top
C2551  22u/6.3V_6  [C0603]  90.49 53.07 270 top
C2552  22u/6.3V_6  [C0603]  89.85 57.82 0 top
C2553  22u/6.3V_6  [C0603]  93.46 53.86 180 top
C2567  *1u/6.3V_4  [C0402]  115.1 37.96 270 top
C2568  18p/50V_4  [C0402]  106.99 40.5 0 bottom
C2569  *EV@0.47u/6.3V_2  [C0201]  104.71 80.89 90 bottom
C2573  150p/50V_4  [C0402]  97.69 35.17 0 bottom
C2574  *1u/6.3V_2  [C0201]  90.54 27.72 270 bottom
C2575  3.9p/50V_4  [C0402]  106.87 38.85 90 bottom
C2576  3.9p/50V_4  [C0402]  106.87 37.07 270 bottom
C2577  15p/50V_4  [C0402]  107 43.42 0 bottom
C2578  150p/50V_4  [C0402]  108.62 34.4 0 bottom
C2579  *100p/50V_4  [C0402]  96.05 30.09 0 top
C2580  15p/50V_4  [C0402]  109.69 47.87 0 bottom
C2593  150p/50V_4  [C0402]  109.15 45.2 90 bottom
C2594  150p/50V_4  [C0402]  108.14 46.06 270 bottom
C2596  220p/25V_2  [C0201]  90.49 79.36 90 bottom
C2631  0.1u/6.3V_2  [C0201]  108.14 62.98 0 bottom
C2632  0.1u/6.3V_2  [C0201]  108.14 62.09 0 bottom
C2633  0.22u/6.3V_2  [C0201]  108.14 66.66 180 bottom
C2634  0.22u/6.3V_2  [C0201]  110.42 66.41 180 bottom
C2635  0.22u/6.3V_2  [C0201]  110.42 65.52 180 bottom
C2636  0.22u/6.3V_2  [C0201]  108.14 65.26 180 bottom
C2637  0.22u/6.3V_2  [C0201]  108.14 64.38 180 bottom
C2638  0.22u/6.3V_2  [C0201]  110.42 64.12 180 bottom
C2639  0.22u/6.3V_2  [C0201]  110.42 63.23 180 bottom
C2640  0.1u/6.3V_2  [C0201]  110.42 61 0 bottom
C2641  0.1u/6.3V_2  [C0201]  110.42 61.84 0 bottom
C2646  0.22u/6.3V_2  [C0201]  108.14 71.23 180 bottom
C2647  0.22u/6.3V_2  [C0201]  108.14 72.12 180 bottom
C2648  0.22u/6.3V_2  [C0201]  110.42 70.09 180 bottom
C2649  0.22u/6.3V_2  [C0201]  110.42 70.98 180 bottom
C2650  0.22u/6.3V_2  [C0201]  108.14 68.95 180 bottom
C2651  0.22u/6.3V_2  [C0201]  108.14 69.84 180 bottom
C2652  0.22u/6.3V_2  [C0201]  110.42 67.8 180 bottom
C2653  0.22u/6.3V_2  [C0201]  110.42 68.69 180 bottom
C2654  0.22u/6.3V_2  [C0201]  108.14 67.55 180 bottom
C2655  *EV@0.1u/16V_4  [C0402]  86.04 89.06 90 bottom
C2656  EV@10P/50V_4  [C0402]  103.06 122.41 0 bottom
C2657  EV@10P/50V_4  [C0402]  105.85 122.41 180 bottom
C2658  EV@1U/6.3V_4  [C0402]  149.03 112 0 top
C2660  EV@0.1U/25V_4  [C0402]  101.03 119.24 270 bottom
C2661  EV@1u/6.3V_2  [C0201]  130.67 115.49 90 bottom
C2662  EV@1U/6.3V_4  [C0402]  130.11 112.38 180 bottom
C2663  EV@0.1U/16V_4  [C0402]  117.66 124.9 270 top
C2665  EV@10u/6.3V_4  [C0402]  144.09 102.11 0 bottom
C2666  *EV@1u/6.3V_2  [C0201]  94.42 98.16 0 bottom
C2667  EV@10u/6.3V_4  [C0402]  138.6 97.39 0 bottom
C2668  *EV@1u/6.3V_2  [C0201]  95.57 98.16 0 bottom
C2669  EV@10u/6.3V_4  [C0402]  105.85 98.28 0 top
C2670  EV@22u/6.3V_6  [C0603]  106.74 96.63 0 top
C2671  EV@1U/6.3V_4  [C0402]  130.39 88.37 180 bottom
C2672  EV@1U/6.3V_4  [C0402]  147.28 79.61 270 bottom
C2673  EV@1U/6.3V_4  [C0402]  141.06 79.48 270 bottom
C2674  *0.047u/16V_4  [C0402]  50.23 52.31 0 top
C2678  0.22u/10V_2  [C0201]  34.86 65.66 0 top
C2679  0.22u/10V_2  [C0201]  42.1 55.1 180 top
C2680  0.22u/10V_2  [C0201]  50.73 84.44 0 top
C2681  0.22u/10V_2  [C0201]  41.08 65.53 0 top
C2682  0.22u/10V_2  [C0201]  43.11 55.1 0 top
C2683  0.22u/10V_2  [C0201]  39.18 43.42 270 top
C2684  0.22u/10V_2  [C0201]  50.73 76.95 0 top
C2685  0.01u/16V_2  [C0201]  31.3 77.96 0 top
C2686  0.01u/16V_2  [C0201]  50.86 45.07 180 top
C2687  0.01u/16V_2  [C0201]  30.62 40.91 90 top
C2688  0.01u/16V_2  [C0201]  39.43 30.85 180 top
C2689  1000p/25V_2  [C0201]  36.13 55.49 0 top
C2690  0.1u/6.3V_2  [C0201]  37.78 77.33 0 top
C2691  1u/6.3V_4  [C0402]  50.08 89.33 180 top
C2692  1u/6.3V_4  [C0402]  46.54 55.23 180 top
C2693  1000p/25V_2  [C0201]  36 76.95 90 top
C2694  0.1u/6.3V_2  [C0201]  38.03 42.15 0 top
C2695  0.22u/10V_2  [C0201]  45.15 55.1 0 top
C2696  0.22u/10V_2  [C0201]  30.67 32.75 270 top
C2697  0.22u/10V_2  [C0201]  43.24 30.85 180 top
C2698  0.22u/10V_2  [C0201]  30.67 33.9 90 top
C2699  0.22u/10V_2  [C0201]  39.94 43.42 270 top
C2700  0.22u/10V_2  [C0201]  50.73 32.24 0 top
C2701  0.01u/16V_2  [C0201]  44.13 55.1 0 top
C2702  0.01u/16V_2  [C0201]  49.59 36.18 270 top
C2703  0.01u/16V_2  [C0201]  30.67 53.2 90 top
C2704  0.01u/16V_2  [C0201]  49.59 34.02 270 top
C2705  1u/6.3V_4  [C0402]  46.8 42.98 180 top
C2706  1u/6.3V_4  [C0402]  46.53 77.14 180 top
C2707  1000p/25V_2  [C0201]  44 91.3 180 top
C2708  0.1u/6.3V_2  [C0201]  44 92.06 0 top
C2709  0.22u/10V_2  [C0201]  50.73 73.77 0 top
C2710  0.22u/10V_2  [C0201]  41.08 55.1 0 top
C2711  0.22u/10V_2  [C0201]  39.94 65.53 0 top
C2712  0.22u/10V_2  [C0201]  50.73 81.52 0 top
C2713  0.22u/10V_2  [C0201]  50.73 86.6 0 top
C2714  0.22u/10V_2  [C0201]  44.38 65.66 0 top
C2715  0.01u/16V_2  [C0201]  50.73 74.92 180 top
C2716  0.01u/16V_2  [C0201]  47.05 91.68 270 top
C2717  0.01u/16V_2  [C0201]  46.29 91.68 270 top
C2718  0.01u/16V_2  [C0201]  30.54 75.04 90 top
C2719  0.22u/10V_2  [C0201]  34.86 92.82 90 top
C2720  0.22u/10V_2  [C0201]  27.37 86.35 180 top
C2721  0.22u/10V_2  [C0201]  38.67 92.82 90 top
C2722  0.22u/10V_2  [C0201]  27.37 88.12 180 top
C2723  0.22u/10V_2  [C0201]  40.07 92.82 90 top
C2724  0.22u/10V_2  [C0201]  27.37 81.27 180 top
C2725  0.22u/10V_2  [C0201]  36.76 92.82 90 top
C2726  0.22u/10V_2  [C0201]  30.92 92.82 90 top
C2727  0.22u/10V_2  [C0201]  27.37 78.85 180 top
C2728  0.22u/10V_2  [C0201]  32.95 92.82 90 top
C2729  0.22u/10V_2  [C0201]  41.59 92.82 90 top
C2730  0.22u/10V_2  [C0201]  27.37 89.9 180 top
C2731  10u/6.3V_4  [C0402]  50.61 48.37 180 top
C2732  10u/6.3V_4  [C0402]  45.27 91.68 270 top
C2733  0.1u/6.3V_2  [C0201]  41.34 78.85 270 top
C2736  HDMI_R@0.1u/10V_2  [C0201]  24.37 77.28 180 top
C2737  HDMI_R@0.1u/10V_2  [C0201]  24.37 78.17 180 top
C2738  HDMI_R@0.1u/10V_2  [C0201]  24.45 79.21 180 top
C2739  HDMI_R@0.1u/10V_2  [C0201]  24.45 80.1 180 top
C2740  HDMI_R@0.1u/10V_2  [C0201]  23.81 81.27 180 top
C2741  HDMI_R@0.1u/10V_2  [C0201]  23.81 82.16 180 top
C2742  HDMI_R@0.1u/10V_2  [C0201]  24.19 75.37 180 top
C2743  HDMI_R@0.1u/10V_2  [C0201]  24.19 76.26 180 top
C2744  0.1u/16V_4  [C0402]  24.19 73.01 270 top
C2745  0.1u/16V_4  [C0402]  25.33 73.01 270 top
C2757  *HUB@0.1U/16V_4  [C0402]  96.45 93.33 90 bottom
C2758  *HUB@0.1U/16V_4  [C0402]  96.2 81.14 270 bottom
C2759  *HUB@0.1U/16V_4  [C0402]  101.41 82.92 0 bottom
C2760  *HUB@1U/6.3V_4  [C0402]  93.03 88.89 90 bottom
C2761  *HUB@1U/6.3V_4  [C0402]  101.41 81.9 0 bottom
C2762  *HUB@0.1U/16V_4  [C0402]  92.26 83.93 270 bottom
C2763  *HUB@10u/6.3V_4  [C0402]  99.63 82.54 180 bottom
C2764  *HUB@0.1U/16V_4  [C0402]  99.63 81.52 180 bottom
C2765  *HUB@22P/50V_4  [C0402]  91.27 84.7 90 bottom
C2766  *HUB@22P/50V_4  [C0402]  91.27 86.47 270 bottom
C2767  *HUB@1u/10V_4  [C0402]  93.15 91.3 270 bottom
C2768  *TPC@220p/50V_4  [C0402]  22.16 15.23 90 bottom
C2769  *TPC@220p/50V_4  [C0402]  21.02 13.7 90 bottom
C2770  *TPC@0.1u/16V_4  [C0402]  21.4 11.54 0 top
C2771  *TPC@0.1u/16V_4  [C0402]  21.4 10.53 0 top
C2772  *TPC@0.33u/6.3V_2  [C0201]  15.68 18.78 0 top
C2773  *TPC@0.33u/6.3V_2  [C0201]  15.68 17.64 0 top
C2774  *TPC@0.1u/16V_4  [C0402]  18.1 11.04 270 top
C2775  *TPC@0.1u/16V_4  [C0402]  19.24 11.04 270 top
C2776  *TPC@0.33u/6.3V_2  [C0201]  15.3 16.5 0 top
C2777  *TPC@0.33u/6.3V_2  [C0201]  15.3 15.35 0 top
C2778  *TPC@0.1u/16V_4  [C0402]  27.37 15.1 270 top
C2779  *TPC@0.1u/16V_4  [C0402]  28.51 15.1 270 top
C2780  *TPC@0.1u/16V_4  [C0402]  29.65 15.1 270 top
C2781  *TPC@0.1u/16V_4  [C0402]  30.67 15.1 270 top
C2782  *TPC@0.1u/16V_4  [C0402]  24.45 14.21 180 top
C2783  *TPC@4.7u/10V_4  [C0402]  21.02 17.77 0 bottom
C2784  *TPC@0.1u/16V_4  [C0402]  22.54 17.39 90 bottom
C2785  *TPC@10u/6.3V_4  [C0402]  21.14 22.26 90 top
C2786  *TPC@10u/6.3V_6  [C0603]  24.06 18.4 0 top
C2787  *TPC@10u/6.3V_6  [C0603]  21.91 22.97 270 bottom
C2788  *TPC@10u/25V_8  [C0805]  11.75 23.48 180 bottom
C2789  *TPC@0.1U/10V_2  [C0201]  23.81 19.67 0 top
C2790  0.1u/16V_2  [C0201]  85.96 28.43 0 bottom
C2792  22p/50V_4  [C0402]  80.08 23.1 0 bottom
C8110  EV@0.22u/6.3V_2  [C0201]  96.45 115.05 0 top
C8115  EV@1U/6.3V_4  [C0402]  107.25 99.55 90 top
C8116  EV@0.22u/6.3V_2  [C0201]  96.45 114.29 0 top
C8118  EV@0.22u/6.3V_2  [C0201]  96.45 112.76 0 top
C8126  EV@0.22u/6.3V_2  [C0201]  96.45 113.52 0 top
C8127  EV@0.22u/6.3V_2  [C0201]  96.45 112 0 top
C8132  EV@0.22u/6.3V_2  [C0201]  96.45 111.24 0 top
C8133  EV@0.22u/6.3V_2  [C0201]  96.45 109.71 0 top
C8134  EV@0.22u/6.3V_2  [C0201]  96.45 110.48 0 top
C8155  *EV@0.1u/16V_4  [C0402]  86.04 86.78 90 bottom
C8164  *HDT@0.01u/10V_2  [C0201]  110.42 43.04 270 bottom
C8165  *HDT@0.1u/10V_2  [C0201]  117.89 46.72 0 top
C28052  *R18M-50@0.082u/16V_4  [C0402]  96.71 102.6 180 bottom
C28053  *R18M-50@0.082u/16V_4  [C0402]  96.71 106.67 180 bottom
C28054  *R18M-50@0.082u/16V_4  [C0402]  96.73 113.52 180 bottom
C28055  *R18M-50@0.082u/16V_4  [C0402]  96.76 110.35 180 bottom
C28062  0.33u/6.3V_2  [C0201]  22.03 32.37 0 top
C28063  0.33u/6.3V_2  [C0201]  22.03 33.39 0 top
C28066  0.33u/6.3V_2  [C0201]  22.16 54.34 0 top
C28067  0.33u/6.3V_2  [C0201]  22.16 55.36 0 top
C96269  0.1u/16V_2  [C0201]  17.46 38.09 180 bottom
C96270  2200p/25V_2  [C0201]  101.66 78.47 90 top
C96271  *EV@0.1u/16V_4  [C0402]  117.03 123.56 90 bottom
C96272  EV@10u/6.3V_4  [C0402]  102.17 121.02 90 bottom
C96274  EV@1u/6.3V_2  [C0201]  118.78 101.64 90 top
C96275  EV@1u/6.3V_2  [C0201]  113.98 96.89 180 top
CN1  *50208-00401-V02  [50208-00401-V02-4P-L]  35.1 118.05 0 bottom
CN2  196538-40041-3  [196538-40041-3-40P-L]  53.47 110.3 0 bottom
CN3  2RJ1622-001111F  [RJ45-2RJ1622-001111F-8P]  10.05 96.2 90 bottom
CN4  10444-19001  [HDMI-10591-19001-19P]  3.4 76.2 90 bottom
CN5  USB3.0 CONN  [UB3-USB-097-1R09HG-9P]  7.4 54.44 90 bottom
CN6  CF34302D0RA-05-NH  [CF34302D0RA-05-NH-30P-L]  218.96 35.65 270 bottom
CN7  USB3.0 CONN  [UB3-USB-097-1R09HG-9P]  7.4 34.44 90 bottom
CN8  FOR14@196153-28021-35  [50584-0280N-V02-28P-L]  140.57 24.2 180 bottom
CN9  NASE0-S6701-TS40  [NGFF-NASE0-S6701-TS40-KE-SMT]  188.5 21.88 270 bottom
CN10  *FOR15_17@196153-28021-35  [50584-0280N-V02-28P-L]  161.5 15.4 180 bottom
CN11  51325-00401-001  [51325-00401-001-4P-L]  117.8 17.6 180 bottom
CN12  51653-0080N-V02  [196047-08021-3-8P-L]  72.82 18.56 180 bottom
CN13  *PBA@196241-08021-3  [196241-08021-3-8P-L]  58.7 18.15 180 bottom
CN14  *TPC@UCF3M-01N01-0P53  [UB31-UCF3M-01N01-0P53-24P]  7.26 15.9 90 bottom
CN15  *ODD@132F18-100000-A2-R  [132F18-100000-A2-R-18P-L]  132.6 14.35 180 bottom
CN16  *KBL@50505-00401-v01-4p-l  [50505-00401-V01-4P-L]  204.32 10.95 180 bottom
CN17  51614-00601-V01  [51614-00601-V01-6P-L]  45.7 8.74 180 bottom
CN18  SSD@NASM0-S6701-TSH4  [NGFF-NASM0-S6701-TSH4-KM-SMT]  30.6 4.35 180 bottom
CN2019  DDR4 STD H=4  [DDR4-D4AS0-26001-1P40-STD-SMT]  54.35 62.83 270 bottom
CN2020  50281-00201-001  [50281-00201-001-2P-L]  14.3 3.45 180 bottom
CN2021  *HDT@HDT CONN  [ASP-137098-05-20P-LDV]  115.89 45.96 270 bottom
D1  1N4148WS  [D-SOD323-1_85X1_25-0_95H]  53.53 103.75 0 top
D3  *PESD5V0H1BSF  [D-0_6X0_3-0_32H-SMT]  18.1 83.43 0 top
D4  *PESD5V0H1BSF  [D-0_6X0_3-0_32H-SMT]  19.49 83.43 180 top
D5  BAT54AW-L  [SOT23-1_7-65-3P]  17.97 86.73 0 top
D8  RB500V-40  [D-1_85X1_25-2P-0_95H]  155.64 14.34 90 top
D9  *RB500V-40  [D-1_85X1_25-2P-0_95H]  159.45 14.34 90 top
D10  TVM0G5R5M220R_22p  [R0402]  162.49 34.91 270 top
D11  *RB500V-40  [D-1_85X1_25-2P-0_95H]  157.54 14.34 90 top
D12  *RB500V-40  [D-1_85X1_25-2P-0_95H]  153.78 14.34 90 top
D13  RB500V-40  [D-1_85X1_25-2P-0_95H]  171.77 22.08 180 bottom
D14  *GS@RB500V-40  [D-1_85X1_25-2P-0_95H]  63.82 21.96 0 top
D15  *GS@RB500V-40  [D-1_85X1_25-2P-0_95H]  67.5 21.96 180 top
D16  *TPM@PESD5V0F1BL  [D-0_6X0_3-0_32H-SMT]  131.14 20.56 270 top
D17  AZ5725-01F.R7G  [ESD-1X0_6-2P]  176.21 19.77 180 bottom
D18  *VPORT_0603_220K-V05  [R0603]  177.15 18.43 180 bottom
D19  *TPC@EGA10402V05AH_0.2p  [R0402]  14.29 8.24 0 top
D21  *VPORT_0603_220K-V05  [R0603]  38.92 121.53 0 top
D22  *VPORT_0603_220K-V05  [R0603]  40.7 121.53 180 bottom
D24  *AZ5725-01F.R7G  [ESD-1X0_6-2P]  15.68 82.16 180 top
D25  *PESD5V0H1BSF  [D-0_6X0_3-0_32H-SMT]  13.78 76.55 270 bottom
D26  *PESD5V0H1BSF  [D-0_6X0_3-0_32H-SMT]  13.78 75.25 90 bottom
D27  *PESD5V0H1BSF  [D-0_6X0_3-0_32H-SMT]  15.07 82.61 270 bottom
D28  *PESD5V0H1BSF  [D-0_6X0_3-0_32H-SMT]  15.07 81.32 90 bottom
D29  *PESD5V0H1BSF  [D-0_6X0_3-0_32H-SMT]  13.78 80.58 270 bottom
D30  *PESD5V0H1BSF  [D-0_6X0_3-0_32H-SMT]  13.78 79.28 90 bottom
D31  *PESD5V0H1BSF  [D-0_6X0_3-0_32H-SMT]  14.82 78.36 270 bottom
D32  *PESD5V0H1BSF  [D-0_6X0_3-0_32H-SMT]  14.82 77.07 90 bottom
D34  1N4148WS  [D-SOD323-1_85X1_25-0_95H]  195.64 31.74 180 bottom
D35  1N4148WS  [D-SOD323-1_85X1_25-0_95H]  197.17 33.13 180 bottom
D36  RB500V-40  [D-1_85X1_25-2P-0_95H]  201.99 17.26 90 top
D37  *RB500V-40  [D-1_85X1_25-2P-0_95H]  194.09 20.41 90 bottom
D38  *TPC@EGA10402V05AH_0.2p  [R0402]  11.24 18.4 0 bottom
D39  *TPC@EGA10402V05AH_0.2p  [R0402]  11.24 19.42 0 top
D41  *TPC@EGA10402V05AH_0.2p  [R0402]  11.62 13.83 0 bottom
D2021  BAT54CW-7-F  [SOT23-1_7-65-3P]  98.08 31.74 0 top
D2024  *B0530WS-7-F  [D-SOD323-1_7X1_3-B0530WS]  112.96 38.85 270 top
D2025  BAT54AW-L  [SOT23-1_7-65-3P]  117.03 38.44 90 top
D2026  RB500V-40  [D-1_85X1_25-2P-0_95H]  88.23 28.71 0 bottom
D2038  RB500V-40  [D-1_85X1_25-2P-0_95H]  112.33 34.28 90 bottom
D2039  RB500V-40  [D-1_85X1_25-2P-0_95H]  110.45 34.02 90 bottom
D2040  *MMC@SDM20U30-7  [D-1_2X0_8-0_7H]  70.42 30.59 0 bottom
D6542  SSD@BAT54AW-L  [SOT23-1_7-65-3P]  68.64 27.98 90 bottom
D6543  BAT54AW-L  [SOT23-1_7-65-3P]  106.74 31.61 90 bottom
D8001  EV@RB500V-40  [D-1_85X1_25-2P-0_95H]  127.09 122.03 270 top
D8509  EV@RB500V-40  [D-1_85X1_25-2P-0_95H]  130.39 122.08 270 top
D8510  *HUB@SDM20U30-7  [D-1_2X0_8-0_7H]  108.82 32.37 90 bottom
D8511  1N4148WS  [D-SOD323-1_85X1_25-0_95H]  21.4 35.04 90 bottom
D8512  1N4148WS  [D-SOD323-1_85X1_25-0_95H]  22.08 38.59 270 bottom
D8513  1N4148WS  [D-SOD323-1_85X1_25-0_95H]  210.88 23.48 180 top
D8514  *RB500V-40  [D-1_85X1_25-2P-0_95H]  151.9 14.34 90 top
D8515  *TPM@SDM20U30-7  [D-1_2X0_8-0_7H]  121.85 24.62 0 top
D8516  *RB500V-40  [D-1_85X1_25-2P-0_95H]  117.41 23.74 0 bottom
EC3  SSD@10u/6.3V_4  [C0402]  23.94 5.57 0 top
EC4  SSD@10u/6.3V_4  [C0402]  25.72 5.57 0 top
EC5  SSD@0.1u/16V_2  [C0201]  25.59 4.56 180 top
EC6  *PBA@AZ5725-01F.R7G  [ESD-1X0_6-2P]  56.91 22.52 0 bottom
EC7  *PBA@AZ5725-01F.R7G  [ESD-1X0_6-2P]  58.78 22.52 0 bottom
EC8  *TPC@22u/6.3V_6  [C0603]  15.3 20.18 180 bottom
EC9  *220p/50V_4  [C0402]  180.91 14.21 180 bottom
EC2007  *180p/25V_2  [C0201]  51.5 70.47 90 top
EC2008  *180p/25V_2  [C0201]  59.75 68.95 90 top
FAN1  50278-00401-001  [WTB-50278-00401-V01-4P-L]  174.73 29.5 90 bottom
FB104  EV@BLM03AX121SN1D  [R0201]  103.19 121.14 90 bottom
HD1  51625-01201-001  [51625-01201-001-12P-L]  217.53 13.57 270 bottom
HE1  APX8132AI-TRG  [SOT23-2_38-95-3P]  34.9 122.75 90 top
HE2  *APX8132AI-TRG  [SOT23-2_38-95-3P]  45.3 122.75 90 top
HOLE2  *SPAD-RE5_98X2_0  [SPAD-RE5_98X2_0]  40.01 123.9 0 top
HOLE3  *h-s157d157n  [H-S157D157N]  121.49 76.98 0 top
HOLE5  *spad-re209x315np  [SPAD-RE209X315NP]  215.74 37.1 0 top
HOLE6  *spad-c354np  [SPAD-C354NP]  41.2 10 0 top
